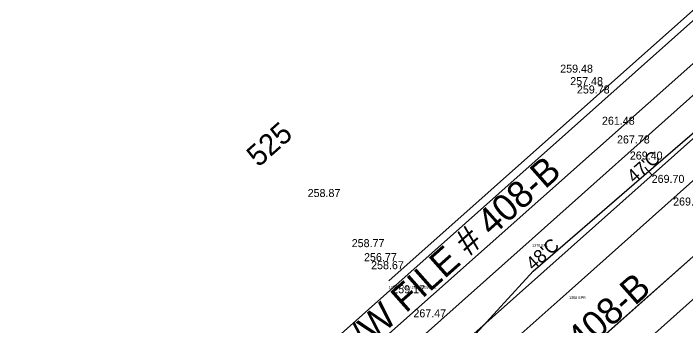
# Model space of a CAD drawing. Extents: x 49683 to 58852, y 49525 to 54803.
# Drawn here: x 53875.1 to 54127.1, y 52022.2 to 52139.1 of the extents above; entities that cross this region are included whole.
import ezdxf

# ---------------------------------------------------------------- set-up
doc = ezdxf.new("R2010")
doc.units = 0
for name, color, linetype in [('Level 1', 7, 'Continuous'), ('Level 11', 7, 'Continuous'), ('Level 13', 7, 'Continuous'), ('Level 18', 7, 'Continuous'), ('Level 19', 7, 'Continuous'), ('Level 20', 7, 'Continuous'), ('Level 21', 7, 'Continuous'), ('Level 25', 7, 'Continuous'), ('Level 3', 7, 'Continuous'), ('Level 32', 7, 'Continuous'), ('Level 48', 7, 'Continuous'), ('Level 53', 7, 'Continuous'), ('Level 58', 7, 'Continuous'), ('Level 8', 7, 'Continuous')]:
    doc.layers.add(name, color=color, linetype=linetype)

msp = doc.modelspace()

# ---------------------------------------------------------------- linework, layer by layer
at = {"layer": 'Level 1'}
for p, q in [((52544.81, 50683.3), (55534.58, 53340.86)), ((54114.5, 52078.58), (54111.84, 52081.57))]:
    msp.add_line(p, q, dxfattribs=at)
at = {"layer": 'Level 11'}
msp.add_line((53894.91, 51911.93), (54324.2, 52292.62), dxfattribs=at)
at = {"layer": 'Level 13'}
for p, q in [((55279.53, 53070), (53969.03, 51905.11)), ((54971.79, 52884.76), (53925.18, 51954.44))]:
    msp.add_line(p, q, dxfattribs=at)
at = {"layer": 'Level 18'}
for p, q in [((54107.86, 52075.28), (54145.7, 52107.97)), ((54070, 52042.61), (54107.86, 52075.28)), ((54036.02, 52005.58), (54070, 52042.61))]:
    msp.add_line(p, q, dxfattribs=at)
at = {"layer": 'Level 19'}
msp.add_line((52714.15, 50773.62), (54181.77, 52078.16), dxfattribs=at)
at = {"layer": 'Level 20'}
msp.add_line((53930.77, 51871.11), (54173.8, 52087.13), dxfattribs=at)
at = {"layer": 'Level 3'}
for p, q in [((54069.54, 52054.72), (54330.23, 52286.79)), ((54083.39, 52035.12), (54346.38, 52269.23)), ((53883.27, 51889.18), (54069.54, 52054.72)), ((53898.74, 51870.57), (54083.39, 52035.12))]:
    msp.add_line(p, q, dxfattribs=at)
at = {"layer": 'Level 8'}
msp.add_line((54015.78, 52039), (54838.64, 52769.14), dxfattribs=at)

# ---------------------------------------------------------------- texts
at = {"layer": 'Level 21'}
msp.add_text('525', height=8, rotation=41.6333, dxfattribs=at).set_placement((53966.97, 52081.24))
at = {"layer": 'Level 25'}
for p in [(53984.2, 51992.86), (54017.83, 51949.17)]:
    msp.add_text("33' R/W FILE # 408-B", height=10, rotation=41.6333, dxfattribs=at).set_placement(p)
at = {"layer": 'Level 32'}
for s, p in [('259.48', (54080.09, 52116.9)), ('257.48', (54083.85, 52112.22)), ('259.78', (54086.35, 52109.1)), ('261.48', (54095.74, 52097.4)), ('267.78', (54101.38, 52090.38)), ('269.40', (54106.2, 52084.37)), ('269.70', (54114.38, 52075.63)), ('258.87', (53985.4, 52070.32)), ('269.44', (54122.42, 52067.15)), ('258.77', (54001.92, 52051.56)), ('256.77', (54006.54, 52046.31)), ('258.67', (54009.19, 52043.3)), ('259.17', (54017.12, 52034.3)), ('267.47', (54025.05, 52025.29))]:
    msp.add_text(s, height=3, dxfattribs=at).set_placement(p)
at = {"layer": 'Level 48'}
for s, p in [("47'C", (54107.86, 52075.28)), ("48'C", (54070, 52042.61))]:
    msp.add_text(s, height=5, rotation=41.6334, dxfattribs=at).set_placement(p)
at = {"layer": 'Level 53'}
for s, p in [('1370 EPL', (54069.54, 52051.72)), ('1368 EPR', (54083.39, 52032.12))]:
    msp.add_text(s, height=1, dxfattribs=at).set_placement(p)
at = {"layer": 'Level 58'}
msp.add_text('1705 FLA O 42IN HOGWIRE', height=1, dxfattribs=at).set_placement((54015.78, 52036))

doc.saveas('drawing.dxf')
